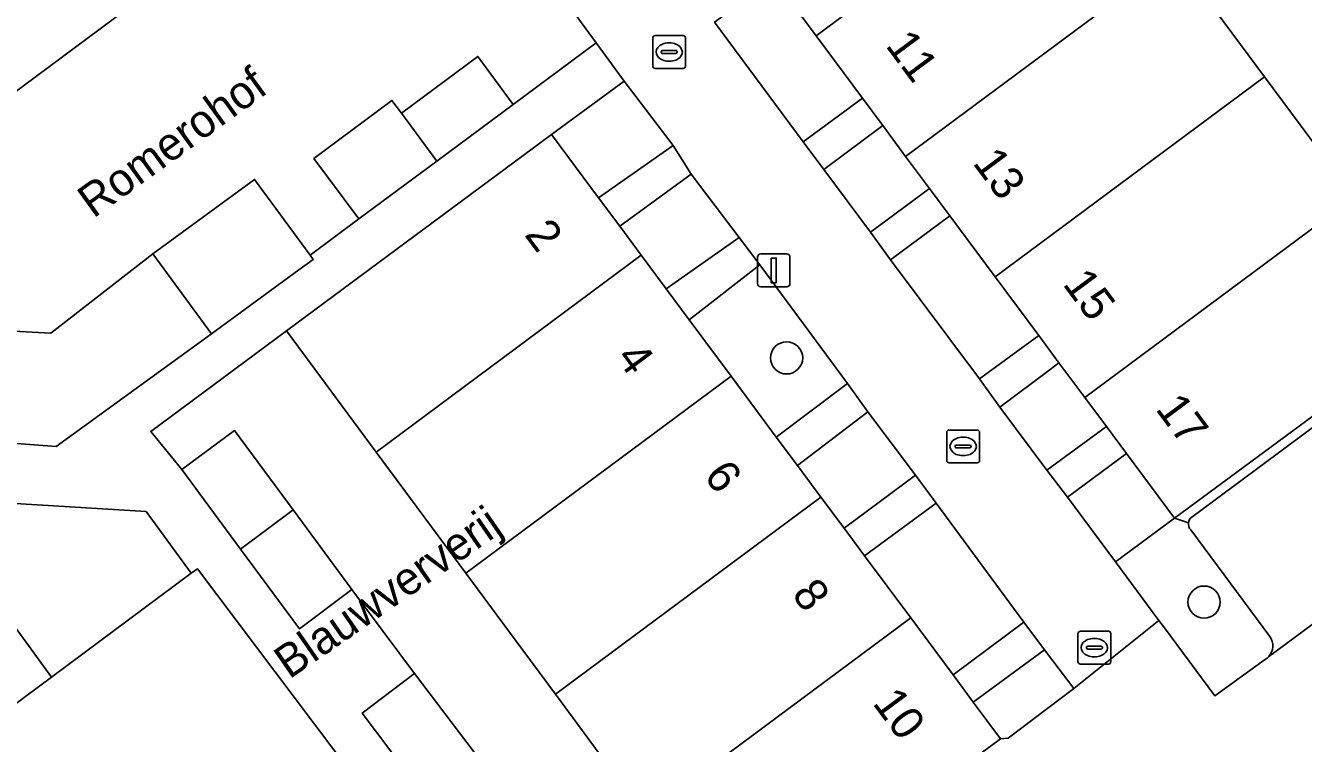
# Model space of a CAD drawing. Extents: x 161798 to 162385, y 382315 to 382833.
# Drawn here: x 162028.08 to 162066.97, y 382454.91 to 382476.77 of the extents above; entities that cross this region are included whole.
import ezdxf

# ---------------------------------------------------------------- set-up
doc = ezdxf.new("R2010")
doc.units = 0
for name, color, linetype in [('IMGEO_Boom', 7, 'Continuous'), ('IMGEO_Erf', 7, 'Continuous'), ('IMGEO_Groenvoorziening', 7, 'Continuous'), ('IMGEO_Kolk', 7, 'Continuous'), ('IMGEO_Lichtmast', 7, 'Continuous'), ('IMGEO_Openbare_ruimte_label', 7, 'Continuous'), ('IMGEO_Pand', 7, 'Continuous'), ('IMGEO_Pand_nummerreeks', 7, 'Continuous'), ('IMGEO_Parkeervlak_open', 7, 'Continuous'), ('IMGEO_Rijbaan_lokaal_open', 7, 'Continuous'), ('IMGEO_Rioolput', 7, 'Continuous'), ('IMGEO_Voetpad_open', 7, 'Continuous')]:
    doc.layers.add(name, color=color, linetype=linetype)

msp = doc.modelspace()

# ---------------------------------------------------------------- linework, layer by layer
at = {"layer": 'IMGEO_Boom'}
for centre in [(162051.24, 382466.65), (162063.944, 382459.218)]:
    msp.add_circle(centre, 0.489, dxfattribs=at)
at = {"layer": 'IMGEO_Erf'}
for points in [[(162021.844, 382467.777), (162028.852, 382467.407), (162031.951, 382469.817), (162035.048, 382472.086), (162036.739, 382469.777), (162038.224, 382470.88), (162036.855, 382472.724), (162039.23, 382474.487), (162039.516, 382474.102), (162041.838, 382475.827), (162042.921, 382474.369), (162045.442, 382476.242), (162034.7, 382490.915), (162033.984, 382491.893), (162033.451, 382491.503), (162022.878, 382483.771)], [(162026.232, 382484.603), (162030.464, 382487.747), (162034.162, 382490.494), (162039.422, 382483.414), (162035.723, 382480.666), (162031.491, 382477.523), (162027.259, 382474.379)], [(162063.065, 382478.878), (162065.787, 382475.204), (162068.51, 382471.53), (162071.252, 382467.829), (162063.042, 382461.773), (162063.468, 382461.63)], [(162063.569, 382461.806), (162075.931, 382470.972)], [(162015.069, 382446.675), (162028.864, 382456.929), (162027.309, 382459.079)]]:
    msp.add_lwpolyline(points, dxfattribs=at)
msp.add_lwpolyline([(162044.202, 382456.411), (162043.211, 382457.751), (162041.477, 382460.097), (162038.752, 382463.783), (162036.02, 382467.479), (162031.888, 382464.407), (162032.833, 382463.25), (162034.439, 382464.437), (162036.226, 382462.021), (162038.012, 382459.604), (162039.918, 382457.045), (162041.729, 382454.653), (162040.915, 382454.037), (162041.8, 382452.86), (162043.565, 382450.429), (162045.33, 382447.999), (162046.218, 382446.777), (162049.647, 382449.044), (162046.927, 382452.724)], close=True, dxfattribs=at)
msp.add_arc((162063.731, 382461.596), 0.265, 127.6785, 172.6216, dxfattribs=at)
at = {"layer": 'IMGEO_Groenvoorziening'}
for points in [[(162052.136, 382476.458), (162050.847, 382478.193), (162049.046, 382476.872), (162051.744, 382473.229), (162053.545, 382474.56)], [(162046.293, 382475.08), (162044.083, 382473.454), (162045.519, 382471.522), (162047.786, 382473.112)], [(162054.863, 382472.787), (162054.168, 382473.722), (162052.372, 382472.386), (162053.788, 382470.482), (162055.592, 382471.805)], [(162048.338, 382472.242), (162046.16, 382470.659), (162046.817, 382469.774), (162047.574, 382468.754), (162049.794, 382470.317)], [(162056.207, 382470.976), (162054.397, 382469.637), (162057.108, 382466.011), (162058.911, 382467.335), (162057.589, 382469.115)], [(162033.734, 382467.382), (162031.951, 382469.817), (162028.852, 382467.407), (162021.844, 382467.777), (162023.567, 382465.307), (162024.49, 382465.967), (162025.798, 382464.194), (162029.013, 382463.958)], [(162050.42, 382469.484), (162048.277, 382467.808), (162049.55, 382466.094), (162050.926, 382464.243), (162053.095, 382465.869)], [(162060.316, 382465.444), (162059.529, 382466.503), (162059.258, 382466.299), (162057.732, 382465.153), (162059.159, 382463.236), (162060.972, 382464.56)], [(162053.712, 382465.013), (162051.568, 382463.379), (162052.284, 382462.415), (162052.988, 382461.467), (162055.167, 382463.079)], [(162061.579, 382463.743), (162059.784, 382462.415), (162061.246, 382460.443), (162063.042, 382461.773)], [(162025.891, 382460.987), (162027.309, 382459.079), (162028.864, 382456.929), (162033.12, 382460.093), (162031.744, 382461.98), (162027.597, 382462.232), (162027.134, 382461.905)], [(162055.793, 382462.225), (162053.614, 382460.624), (162055.017, 382458.735), (162056.305, 382457.001), (162058.455, 382458.611)], [(162059.092, 382457.759), (162056.921, 382456.172), (162057.751, 382455.055), (162057.986, 382455.074), (162059.982, 382456.586)]]:
    msp.add_lwpolyline(points, close=True, dxfattribs=at)
for points in [[(162063.468, 382461.63), (162063.042, 382461.773), (162061.246, 382460.443), (162062.57, 382458.658), (162062.709, 382458.471), (162064.275, 382456.359), (162065.818, 382457.478)], [(162065.949, 382458.172), (162063.537, 382461.412)]]:
    msp.add_lwpolyline(points, dxfattribs=at)
for centre, radius, start, end in [((162063.732, 382461.594), 0.266, 172.1568, 222.9698), ((162065.542, 382457.889), 0.495, 317.2389, 34.8135), ((162065.524, 382457.912), 0.524, 304.1036, 316.7765)]:
    msp.add_arc(centre, radius, start, end, dxfattribs=at)
at = {"layer": 'IMGEO_Kolk'}
for p, q in [((162047.165, 382475.537), (162047.165, 382476.389)), ((162047.24, 382476.463), (162048.092, 382476.463)), ((162047.653, 382476.243), (162047.678, 382476.243)), ((162048.166, 382476.389), (162048.166, 382475.537)), ((162047.424, 382475.957), (162047.424, 382475.969)), ((162047.862, 382475.92), (162047.464, 382475.92)), ((162047.467, 382476.006), (162047.865, 382476.006)), ((162047.908, 382475.969), (162047.908, 382475.957)), ((162048.092, 382475.463), (162047.24, 382475.463)), ((162047.676, 382475.683), (162047.651, 382475.683)), ((162056.187, 382464.456), (162057.039, 382464.456)), ((162056.112, 382463.53), (162056.112, 382464.382)), ((162056.6, 382464.236), (162056.625, 382464.236)), ((162057.113, 382464.382), (162057.113, 382463.53)), ((162056.371, 382463.95), (162056.371, 382463.962)), ((162056.809, 382463.913), (162056.411, 382463.913)), ((162056.414, 382463.999), (162056.812, 382463.999)), ((162056.623, 382463.676), (162056.598, 382463.676)), ((162056.855, 382463.962), (162056.855, 382463.95)), ((162057.039, 382463.456), (162056.187, 382463.456))]:
    msp.add_line(p, q, dxfattribs=at)
for points in [[(162047.165, 382475.537), (162047.165, 382476.389)], [(162047.24, 382476.463), (162048.092, 382476.463)], [(162048.166, 382476.389), (162048.166, 382475.537)], [(162048.092, 382475.463), (162047.24, 382475.463)], [(162056.187, 382464.456), (162057.039, 382464.456)], [(162056.112, 382463.53), (162056.112, 382464.382)], [(162057.113, 382464.382), (162057.113, 382463.53)], [(162057.039, 382463.456), (162056.187, 382463.456)]]:
    msp.add_lwpolyline(points, dxfattribs=at)
for centre, radius, start, end in [((162047.242, 382476.387), 0.0765, 91.552, 178.448), ((162047.242, 382476.387), 0.0765, 91.552, 178.448), ((162048.09, 382476.387), 0.0765, 1.552, 88.448), ((162048.09, 382476.387), 0.0765, 1.552, 88.448), ((162047.464, 382475.966), 0.0403, 85.8775, 175.7526), ((162047.461, 382475.956), 0.0366, 178.938, 274.7102), ((162047.865, 382475.963), 0.043, 264.8664, 352.4533), ((162047.869, 382475.968), 0.0386, 1.7309, 96.639), ((162047.242, 382475.539), 0.0765, 181.552, 268.448), ((162047.242, 382475.539), 0.0765, 181.552, 268.448), ((162048.09, 382475.539), 0.0765, 271.552, 358.448), ((162048.09, 382475.539), 0.0765, 271.552, 358.448), ((162056.189, 382464.38), 0.0765, 91.552, 178.448), ((162056.189, 382464.38), 0.0765, 91.552, 178.448), ((162057.037, 382464.38), 0.0765, 1.552, 88.448), ((162057.037, 382464.38), 0.0765, 1.552, 88.448), ((162056.411, 382463.959), 0.0403, 85.8775, 175.7526), ((162056.408, 382463.949), 0.0366, 178.938, 274.7102), ((162056.812, 382463.956), 0.043, 264.8664, 352.4533), ((162056.816, 382463.961), 0.0386, 1.7309, 96.639), ((162056.189, 382463.532), 0.0765, 181.552, 268.448), ((162056.189, 382463.532), 0.0765, 181.552, 268.448), ((162057.037, 382463.532), 0.0765, 271.552, 358.448), ((162057.037, 382463.532), 0.0765, 271.552, 358.448)]:
    msp.add_arc(centre, radius, start, end, dxfattribs=at)
for centre, major_axis, ratio, start_param, end_param in [((162047.652, 382475.963), (-0.387, 0.002), 0.722429, 4.712389, 7.853982), ((162047.677, 382475.963), (-0.39, 0.002), 0.717154, 1.570796, 4.712389), ((162056.599, 382463.956), (-0.387, 0.002), 0.722429, 4.712389, 7.853982), ((162056.624, 382463.956), (-0.39, 0.002), 0.717154, 1.570796, 4.712389)]:
    msp.add_ellipse(centre, major_axis=major_axis, ratio=ratio, start_param=start_param, end_param=end_param, dxfattribs=at)
at = {"layer": 'IMGEO_Lichtmast'}
for p, q in [((162050.352, 382468.914), (162050.352, 382469.714)), ((162050.352, 382469.714), (162050.352, 382468.914)), ((162050.452, 382469.814), (162051.242, 382469.814)), ((162051.242, 382469.814), (162050.452, 382469.814)), ((162051.342, 382469.714), (162051.342, 382468.914)), ((162051.342, 382468.914), (162051.342, 382469.714)), ((162051.242, 382468.814), (162050.452, 382468.814)), ((162050.452, 382468.814), (162051.242, 382468.814))]:
    msp.add_line(p, q, dxfattribs=at)
msp.add_lwpolyline([(162050.772, 382469.689), (162050.922, 382469.689), (162050.922, 382468.939), (162050.772, 382468.939), (162050.772, 382469.689)], dxfattribs=at)
for centre, start, end in [((162050.452, 382469.714), 90, 180), ((162050.452, 382469.714), 90, 180), ((162051.242, 382469.714), 0, 90), ((162051.242, 382469.714), 360, 90), ((162050.452, 382468.914), 180, 270), ((162050.452, 382468.914), 180, 270), ((162051.242, 382468.914), 270, 0), ((162051.242, 382468.914), 270, 0)]:
    msp.add_arc(centre, 0.1, start, end, dxfattribs=at)
at = {"layer": 'IMGEO_Pand'}
for points in [[(162060.342, 382482.552), (162057.62, 382486.226), (162049.409, 382480.129), (162050.22, 382479.038), (162050.847, 382478.193), (162052.136, 382476.458)], [(162031.491, 382477.523), (162026.232, 382484.603), (162022, 382481.459), (162027.259, 382474.379)], [(162063.065, 382478.878), (162060.342, 382482.552), (162052.136, 382476.458), (162053.545, 382474.56), (162054.168, 382473.722), (162054.863, 382472.787)], [(162065.787, 382475.204), (162063.065, 382478.878), (162054.863, 382472.787), (162055.592, 382471.805), (162056.207, 382470.976), (162057.589, 382469.115)], [(162039.516, 382474.102), (162040.599, 382472.644), (162042.921, 382474.369), (162041.838, 382475.827)], [(162068.51, 382471.53), (162065.787, 382475.204), (162057.589, 382469.115), (162058.911, 382467.335), (162059.529, 382466.503), (162060.316, 382465.444)], [(162040.599, 382472.644), (162039.516, 382474.102), (162039.23, 382474.487), (162036.855, 382472.724), (162038.224, 382470.88)], [(162046.817, 382469.774), (162046.16, 382470.659), (162045.519, 382471.522), (162044.083, 382473.454), (162037.158, 382468.322), (162036.02, 382467.479), (162038.752, 382463.783)], [(162036.831, 382469.651), (162036.739, 382469.777), (162035.048, 382472.086), (162031.951, 382469.817), (162033.734, 382467.382), (162036.397, 382469.333)], [(162071.252, 382467.829), (162068.51, 382471.53), (162060.316, 382465.444), (162060.972, 382464.56), (162061.579, 382463.743), (162063.042, 382461.773)], [(162049.55, 382466.094), (162048.277, 382467.808), (162047.574, 382468.754), (162046.817, 382469.774), (162038.752, 382463.783), (162041.477, 382460.097)], [(162052.284, 382462.415), (162051.568, 382463.379), (162050.926, 382464.243), (162049.55, 382466.094), (162041.477, 382460.097), (162043.211, 382457.751), (162044.202, 382456.411)], [(162034.439, 382464.437), (162032.833, 382463.25), (162034.62, 382460.833), (162036.226, 382462.021)], [(162055.017, 382458.735), (162053.614, 382460.624), (162052.988, 382461.467), (162052.284, 382462.415), (162044.202, 382456.411), (162046.927, 382452.724)], [(162036.226, 382462.021), (162034.62, 382460.833), (162036.42, 382458.399), (162038.012, 382459.604)], [(162039.058, 382452.455), (162038.02, 382453.975), (162033.309, 382460.233), (162033.12, 382460.093), (162028.864, 382456.929), (162015.069, 382446.675), (162016.135, 382445.239), (162019.568, 382440.542), (162020.713, 382438.983)], [(162057.751, 382455.055), (162056.921, 382456.172), (162056.305, 382457.001), (162055.017, 382458.735), (162046.927, 382452.724), (162049.647, 382449.044)], [(162039.918, 382457.045), (162038.324, 382455.838), (162040.133, 382453.445), (162040.915, 382454.037), (162041.729, 382454.653)]]:
    msp.add_lwpolyline(points, close=True, dxfattribs=at)
at = {"layer": 'IMGEO_Parkeervlak_open'}
for points in [[(162075.931, 382470.972), (162063.569, 382461.806)], [(162065.906, 382457.553), (162079.043, 382467.284)], [(162063.537, 382461.412), (162065.949, 382458.172)]]:
    msp.add_lwpolyline(points, dxfattribs=at)
for centre, radius, start, end in [((162063.731, 382461.596), 0.265, 127.6785, 172.6216), ((162063.732, 382461.594), 0.266, 172.1568, 222.9698), ((162065.542, 382457.889), 0.495, 317.2389, 34.8135)]:
    msp.add_arc(centre, radius, start, end, dxfattribs=at)
at = {"layer": 'IMGEO_Rijbaan_lokaal_open'}
for points in [[(162066.998, 382448.171), (162065.693, 382450.051), (162072.121, 382454.773), (162072.399, 382454.977), (162080.992, 382461.339), (162082.387, 382459.443), (162083.88, 382460.516), (162082.212, 382462.98), (162079.043, 382467.284), (162065.906, 382457.553)], [(162065.818, 382457.478), (162064.275, 382456.359), (162062.709, 382458.471), (162062.57, 382458.658), (162059.982, 382456.586), (162057.986, 382455.074), (162057.751, 382455.055), (162049.647, 382449.044), (162046.218, 382446.777), (162042.301, 382443.865), (162039.786, 382441.995), (162037.165, 382440.047), (162033.192, 382437.094), (162030.663, 382435.214), (162025.905, 382431.677)]]:
    msp.add_lwpolyline(points, dxfattribs=at)
msp.add_arc((162065.524, 382457.912), 0.524, 304.1036, 316.7765, dxfattribs=at)
at = {"layer": 'IMGEO_Rioolput'}
for p, q in [((162060.106, 382457.405), (162060.106, 382458.257)), ((162060.181, 382458.331), (162061.033, 382458.331)), ((162061.107, 382458.257), (162061.107, 382457.405)), ((162060.365, 382457.825), (162060.365, 382457.837)), ((162060.408, 382457.874), (162060.806, 382457.874)), ((162060.594, 382458.111), (162060.619, 382458.111)), ((162060.849, 382457.837), (162060.849, 382457.825)), ((162060.803, 382457.788), (162060.405, 382457.788)), ((162060.617, 382457.551), (162060.592, 382457.551)), ((162061.033, 382457.331), (162060.181, 382457.331))]:
    msp.add_line(p, q, dxfattribs=at)
for points in [[(162060.106, 382457.405), (162060.106, 382458.257)], [(162060.181, 382458.331), (162061.033, 382458.331)], [(162061.107, 382458.257), (162061.107, 382457.405)], [(162061.033, 382457.331), (162060.181, 382457.331)]]:
    msp.add_lwpolyline(points, dxfattribs=at)
for centre, radius, start, end in [((162060.183, 382458.255), 0.0765, 91.552, 178.448), ((162060.183, 382458.255), 0.0765, 91.552, 178.448), ((162061.031, 382458.255), 0.0765, 1.552, 88.448), ((162061.031, 382458.255), 0.0765, 1.552, 88.448), ((162060.405, 382457.834), 0.0403, 85.8775, 175.7526), ((162060.402, 382457.824), 0.0366, 178.938, 274.7102), ((162060.806, 382457.831), 0.043, 264.8664, 352.4533), ((162060.81, 382457.836), 0.0386, 1.7309, 96.639), ((162060.183, 382457.407), 0.0765, 181.552, 268.448), ((162060.183, 382457.407), 0.0765, 181.552, 268.448), ((162061.031, 382457.407), 0.0765, 271.552, 358.448), ((162061.031, 382457.407), 0.0765, 271.552, 358.448)]:
    msp.add_arc(centre, radius, start, end, dxfattribs=at)
for centre, major_axis, ratio, start_param, end_param in [((162060.593, 382457.831), (-0.387, 0.002), 0.722429, 4.712389, 7.853982), ((162060.618, 382457.831), (-0.39, 0.002), 0.717154, 1.570796, 4.712389)]:
    msp.add_ellipse(centre, major_axis=major_axis, ratio=ratio, start_param=start_param, end_param=end_param, dxfattribs=at)
at = {"layer": 'IMGEO_Voetpad_open'}
for points in [[(162034.7, 382490.915), (162045.442, 382476.242), (162046.293, 382475.08), (162047.786, 382473.112), (162048.338, 382472.242), (162049.794, 382470.317), (162050.42, 382469.484), (162053.095, 382465.869), (162053.712, 382465.013), (162055.167, 382463.079), (162055.793, 382462.225), (162058.455, 382458.611), (162059.092, 382457.759), (162059.982, 382456.586), (162062.57, 382458.658), (162061.246, 382460.443), (162059.784, 382462.415), (162059.159, 382463.236), (162057.732, 382465.153), (162057.108, 382466.011), (162054.397, 382469.637), (162053.788, 382470.482), (162052.372, 382472.386), (162051.744, 382473.229), (162049.046, 382476.872)], [(162040.133, 382453.445), (162038.324, 382455.838), (162039.918, 382457.045), (162038.012, 382459.604), (162036.42, 382458.399), (162034.62, 382460.833), (162032.833, 382463.25), (162031.888, 382464.407), (162036.02, 382467.479), (162037.158, 382468.322), (162044.083, 382473.454), (162046.293, 382475.08), (162045.442, 382476.242), (162042.921, 382474.369), (162040.599, 382472.644), (162038.224, 382470.88), (162036.739, 382469.777), (162036.831, 382469.651), (162036.397, 382469.333), (162033.734, 382467.382), (162029.013, 382463.958), (162025.798, 382464.194)], [(162027.597, 382462.232), (162031.744, 382461.98), (162033.12, 382460.093), (162033.309, 382460.233), (162038.02, 382453.975)]]:
    msp.add_lwpolyline(points, dxfattribs=at)
for points in [[(162054.168, 382473.722), (162053.545, 382474.56), (162051.744, 382473.229), (162052.372, 382472.386)], [(162048.338, 382472.242), (162047.786, 382473.112), (162045.519, 382471.522), (162046.16, 382470.659)], [(162056.207, 382470.976), (162055.592, 382471.805), (162053.788, 382470.482), (162054.397, 382469.637)], [(162050.42, 382469.484), (162049.794, 382470.317), (162047.574, 382468.754), (162048.277, 382467.808)], [(162059.529, 382466.503), (162058.911, 382467.335), (162057.108, 382466.011), (162057.732, 382465.153), (162059.258, 382466.299)], [(162053.712, 382465.013), (162053.095, 382465.869), (162050.926, 382464.243), (162051.568, 382463.379)], [(162061.579, 382463.743), (162060.972, 382464.56), (162059.159, 382463.236), (162059.784, 382462.415)], [(162055.793, 382462.225), (162055.167, 382463.079), (162052.988, 382461.467), (162053.614, 382460.624)], [(162059.092, 382457.759), (162058.455, 382458.611), (162056.305, 382457.001), (162056.921, 382456.172)]]:
    msp.add_lwpolyline(points, close=True, dxfattribs=at)

# ---------------------------------------------------------------- texts
at = {"layer": 'IMGEO_Openbare_ruimte_label'}
for s, rotation, p in [('Romerohof', 35.8041, (162030.141, 382470.882)), ('Blauwververij', 34.6915, (162036.104, 382456.853))]:
    msp.add_text(s, height=1, rotation=rotation, dxfattribs=at).set_placement(p)
at = {"layer": 'IMGEO_Pand_nummerreeks'}
for s, rotation, p in [('11', 306.6003, (162054.228, 382476.157)), ('13', 306.6003, (162056.883, 382472.582)), ('2', 306.6061, (162043.239, 382470.398)), ('15', 306.6003, (162059.62, 382468.896)), ('4', 306.6061, (162046.021, 382466.652)), ('17', 306.6003, (162062.445, 382465.093)), ('6', 306.6061, (162048.696, 382463.052)), ('8', 306.6061, (162051.373, 382459.448)), ('10', 306.6061, (162053.835, 382456.135))]:
    msp.add_text(s, height=1, rotation=rotation, dxfattribs=at).set_placement(p)

doc.saveas('drawing.dxf')
